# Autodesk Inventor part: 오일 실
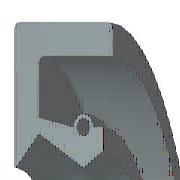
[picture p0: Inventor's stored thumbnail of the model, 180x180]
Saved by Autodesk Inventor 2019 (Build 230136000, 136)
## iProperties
IsCustomPart: 0
Created: 2014-10
Part Number: 오일 실
Material: 고무
Description: 오일-실
Document SubType Name: Modeling
Standard: KS B 2804
Designer: KYOUNG IL JANG
Standards Organization: KS
Language: ko-KR
Size Designation: D - 17 32 8
Categories: <MemberInstance><Categories><Category DisplayName="샤프트 부품" InternalName="7f7aeb1f-a693-4053-b835-cee3144e0d98" Mnemonic="SHFT"><Category DisplayName="실링" Intern
Density: 0.93 g/cm^3
Mass: 2.28027 g
Surface Area: 32.1224 cm^2
Volume: 2.45191 cm^3
Appearance: 고무 - 검은색 - 버전 1.1
Author: SeoGD™ [www.esajin.kr]
Revision Number: 1
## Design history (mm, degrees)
revolve "본체" stored, may be unused: angle "d17" = 90 deg
revolve "스프링1" stored, may be unused: angle "d18" = 90 deg
body "Solid1"
sketch "스케치1"
  geometry: L1 (0, 16)-(8, 16); L2 (8, 14.25)-(1.75, 14.25); L3 (1.75, 10.25)-(4.9, 8.5); L4 (4.9, 8.5)-(0, 8.5); L5 (0, 0)-(9.586, 0) reference; L6 (4.9, 8.5)-(6.3, 9.375); L7 (0, 18)-(0, -3) reference; L8 (-1.941, 0)-(11.507, 0) reference; L9 (4.2, 10.6)-(1.75, 11.21); L10 (1.75, 11.21)-(1.75, 14.25); L11 (0, 16)-(0, 8.588); L12 (4.9, 8.5)-(0, 8.5); L13 (1.75, 10.25)-(0.152, 8.528); L14 (8, 16)-(8, 14.25); L15 (5.6, 10.6)-(6.3, 10.6); L16 (6.3, 10.6)-(6.3, 9.375); C1 r 0.455 at (4.9, 10.6); A1 r 0.7 centre (4.9, 10.6) between (5.6, 10.6) and (4.2, 10.6); A2 r 0.088 centre (0.088, 8.588) between (0, 8.588) and (0.152, 8.528); 1 further point
  constraints: 28 end point, 5 horizontal alignment, 5 point on line, 4 point on circle, 4 vertical alignment, 3 centre point, 3 tangent, 2 collinear, 2 horizontal, 2 perpendicular, 1 coincident, 1 parallel
  dimensions: "d0" = 32 diameter of L1 L5 (= SD2); "d1" = 1.75 distance of L1.end L2.start (= SD); "d2" = 0.91 diameter of C1 (= SPDI); "d3" = 1.4 diameter of A1 (= SPDA); "d4" = 17 diameter of L3.end L5 (= NND); "d5" = 20.5 diameter of L3.start L5 (= TKDM); "d7" = 22.42 diameter of L9.end L5 (= TKDM + 0.24 x SWDT); "d8" = 1.75 distance between parallel lines of L11 L10 (= SD); "d9" = 4.9 distance from line of L11 C1.centre (= SPDST); "d10" = 21.2 diameter of C1.centre L5 (= HLDM); "d11" = 0.0875 radius of A2 (= 0.25 x LAB); "d12" = 6.3 distance between parallel lines of L11 L16 (= SDI); "d13" = 18.75 diameter of L6.end L5 (= ABDM); "d14" = 8 distance from line of L11 L1.end (= SWDT)
fillet "모깎기1" dims "d6" = 0.3 (= RR)
other parameters: "SD2" = 32 [user parameter; used in 1 equation term], "SWDT" = 8 [user parameter; used in 2 equation terms], "RR" = 0.3 [user parameter; used in 1 equation term], "SD" = 1.75 [user parameter; used in 2 equation terms], "NND" = 17 [user parameter; used in 1 equation term], "SPDA" = 1.4 [user parameter; used in 1 equation term], "SPDI" = 0.91 [user parameter; used in 1 equation term], "TKDM" = 20.5 [user parameter; used in 2 equation terms], "HLDM" = 21.2 [user parameter; used in 1 equation term], "ABDM" = 18.75 [user parameter; used in 1 equation term], "SDI" = 6.3 [user parameter; used in 1 equation term], "SPDST" = 4.9 [user parameter; used in 1 equation term], "LAB" = 0.35 [user parameter; used in 1 equation term], "d15" = 0, "d16" = 0, "d19" = 0
